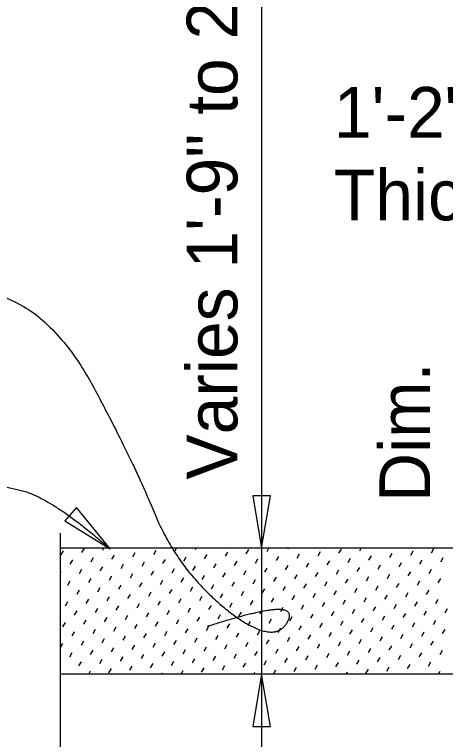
# Model space of a CAD drawing. Extents: x 0 to 41.1, y 0 to 25.9.
# Drawn here: x 3.953 to 5.668, y 17.261 to 20.145 of the extents above; entities that cross this region are included whole.
import ezdxf

# ---------------------------------------------------------------- set-up
doc = ezdxf.new("R2010")
doc.units = 0
for name, color, linetype in [('Dimension', 7, 'Continuous'), ('ExistSuperStruct', 7, 'Continuous'), ('Miscellaneous', 7, 'Continuous'), ('TextStructures', 7, 'Continuous')]:
    doc.layers.add(name, color=color, linetype=linetype)

msp = doc.modelspace()

# ---------------------------------------------------------------- linework, layer by layer
at = {"layer": 'Dimension'}
msp.add_line((4.936, 23.3552), (4.936, 16.3552), dxfattribs=at)
for points in [[(4.936, 18.0218), (4.9712, 18.2301), (4.9007, 18.2301)], [(4.3332, 18.0199), (4.1998, 18.1836), (4.1533, 18.1305)], [(4.936, 17.5218), (4.9007, 17.3136), (4.9712, 17.3136)]]:
    msp.add_lwpolyline(points, close=True, dxfattribs=at)
msp.add_lwpolyline([(4.1358, 16.1947), (4.1358, 17.0945), (4.0325, 17.0945), (4.1358, 17.1395), (4.2391, 17.1845), (4.1358, 17.1845), (4.1358, 18.0815)], dxfattribs=at)
for points in [[(2.6424, 19.1697), (3.0627, 19.1697), (3.7101, 19.0924), (4.1159, 18.9475), (4.4299, 18.3581), (4.5748, 18.0006), (4.8018, 17.7591), (4.9951, 17.6624), (5.0724, 17.7784), (4.9323, 17.7784), (4.7197, 17.7108)], [(3.0724, 18.3484), (3.3332, 18.3484), (3.6038, 18.3484), (3.8598, 18.2808), (4.1014, 18.2228), (4.3332, 18.0199)]]:
    msp.add_open_spline(points, degree=2, dxfattribs=at)
at = {"layer": 'ExistSuperStruct'}
msp.add_line((8.069, 17.5218), (4.1357, 17.5218), dxfattribs=at)
at = {"layer": 'Miscellaneous'}
for p, q in [((8.1278, 18.0218), (4.1357, 18.0218)), ((4.1385, 17.9954), (4.1482, 18.0122)), ((4.2214, 18.0051), (4.2311, 18.0218)), ((4.3044, 18.0148), (4.3084, 18.0218)), ((4.341, 17.9782), (4.3507, 17.995)), ((4.4239, 17.9879), (4.4336, 18.0047)), ((4.5068, 17.9976), (4.5166, 18.0144)), ((4.5898, 18.0074), (4.5981, 18.0218)), ((4.6727, 18.0171), (4.6755, 18.0218)), ((4.7093, 17.9805), (4.719, 17.9973)), ((4.7923, 17.9902), (4.802, 18.007)), ((4.8752, 17.9999), (4.8849, 18.0167)), ((4.9581, 18.0097), (4.9652, 18.0218)), ((5.0411, 18.0194), (5.0425, 18.0218)), ((5.0777, 17.9828), (5.0874, 17.9996)), ((5.1606, 17.9925), (5.1703, 18.0093)), ((5.2436, 18.0022), (5.2533, 18.019)), ((5.3265, 18.0119), (5.3322, 18.0218)), ((5.4094, 18.0217), (5.4095, 18.0218)), ((5.446, 17.9851), (5.4558, 18.0018)), ((5.529, 17.9948), (5.5387, 18.0116)), ((5.6119, 18.0045), (5.6216, 18.0213)), ((4.1751, 17.9588), (4.1848, 17.9756)), ((4.258, 17.9685), (4.2678, 17.9853)), ((4.4605, 17.9513), (4.4702, 17.9681)), ((4.5434, 17.961), (4.5532, 17.9778)), ((4.6264, 17.9708), (4.6361, 17.9876)), ((4.8289, 17.9536), (4.8386, 17.9704)), ((4.9118, 17.9633), (4.9215, 17.9801)), ((4.9947, 17.973), (5.0045, 17.9898)), ((5.1972, 17.9559), (5.207, 17.9727)), ((5.2802, 17.9656), (5.2899, 17.9824)), ((5.3631, 17.9753), (5.3728, 17.9921)), ((5.5656, 17.9582), (5.5753, 17.975)), ((5.6485, 17.9679), (5.6582, 17.9847)), ((4.2117, 17.9221), (4.2214, 17.9389)), ((4.2946, 17.9319), (4.3044, 17.9487)), ((4.3776, 17.9416), (4.3873, 17.9584)), ((4.5801, 17.9244), (4.5898, 17.9412)), ((4.663, 17.9342), (4.6727, 17.9509)), ((4.7459, 17.9439), (4.7557, 17.9607)), ((4.9484, 17.9267), (4.9581, 17.9435)), ((5.0314, 17.9364), (5.0411, 17.9532)), ((5.1143, 17.9462), (5.124, 17.963)), ((5.3168, 17.929), (5.3265, 17.9458)), ((5.3997, 17.9387), (5.4094, 17.9555)), ((5.4826, 17.9484), (5.4924, 17.9652)), ((5.6022, 17.9216), (5.6119, 17.9384)), ((4.1357, 17.9244), (4.1385, 17.9292)), ((4.3312, 17.8953), (4.341, 17.9121)), ((4.4142, 17.905), (4.4239, 17.9218)), ((4.4971, 17.9147), (4.5068, 17.9315)), ((4.6996, 17.8975), (4.7093, 17.9143)), ((4.7825, 17.9073), (4.7923, 17.9241)), ((4.8655, 17.917), (4.8752, 17.9338)), ((5.068, 17.8998), (5.0777, 17.9166)), ((5.1509, 17.9096), (5.1606, 17.9263)), ((5.2338, 17.9193), (5.2436, 17.9361)), ((5.3534, 17.8924), (5.3631, 17.9092)), ((5.4363, 17.9021), (5.446, 17.9189)), ((5.5193, 17.9118), (5.529, 17.9286)), ((4.1654, 17.8758), (4.1751, 17.8926)), ((4.2483, 17.8855), (4.258, 17.9023)), ((4.4508, 17.8684), (4.4605, 17.8852)), ((4.5337, 17.8781), (4.5434, 17.8949)), ((4.6167, 17.8878), (4.6264, 17.9046)), ((4.8191, 17.8707), (4.8289, 17.8875)), ((4.9021, 17.8804), (4.9118, 17.8972)), ((4.985, 17.8901), (4.9947, 17.9069)), ((5.1046, 17.8632), (5.1143, 17.88)), ((5.1875, 17.8729), (5.1972, 17.8897)), ((5.2704, 17.8827), (5.2802, 17.8995)), ((5.4729, 17.8655), (5.4826, 17.8823)), ((5.5559, 17.8752), (5.5656, 17.892)), ((5.6388, 17.885), (5.6485, 17.9017)), ((4.202, 17.8392), (4.2117, 17.856)), ((4.2849, 17.8489), (4.2946, 17.8657)), ((4.3679, 17.8587), (4.3776, 17.8755)), ((4.5703, 17.8415), (4.5801, 17.8583)), ((4.6533, 17.8512), (4.663, 17.868)), ((4.7362, 17.8609), (4.7459, 17.8777)), ((4.8558, 17.8341), (4.8655, 17.8508)), ((4.9387, 17.8438), (4.9484, 17.8606)), ((5.0216, 17.8535), (5.0314, 17.8703)), ((5.2241, 17.8363), (5.2338, 17.8531)), ((5.3071, 17.8461), (5.3168, 17.8629)), ((5.39, 17.8558), (5.3997, 17.8726)), ((5.5925, 17.8386), (5.6022, 17.8554)), ((4.3215, 17.8123), (4.3312, 17.8291)), ((4.4045, 17.822), (4.4142, 17.8388)), ((4.4874, 17.8318), (4.4971, 17.8486)), ((4.6069, 17.8049), (4.6167, 17.8217)), ((4.6899, 17.8146), (4.6996, 17.8314)), ((4.7728, 17.8243), (4.7825, 17.8411)), ((4.9753, 17.8072), (4.985, 17.824)), ((5.0582, 17.8169), (5.068, 17.8337)), ((5.1412, 17.8266), (5.1509, 17.8434)), ((5.3437, 17.8095), (5.3534, 17.8262)), ((5.4266, 17.8192), (5.4363, 17.836)), ((5.5095, 17.8289), (5.5193, 17.8457)), ((4.1556, 17.7929), (4.1654, 17.8097)), ((4.2386, 17.8026), (4.2483, 17.8194)), ((4.4411, 17.7854), (4.4508, 17.8022)), ((4.524, 17.7952), (4.5337, 17.812)), ((4.7265, 17.778), (4.7362, 17.7948)), ((4.8094, 17.7877), (4.8191, 17.8045)), ((4.8924, 17.7974), (4.9021, 17.8142)), ((5.0948, 17.7803), (5.1046, 17.7971)), ((5.1778, 17.79), (5.1875, 17.8068)), ((5.2607, 17.7997), (5.2704, 17.8165)), ((5.4632, 17.7826), (5.4729, 17.7994)), ((5.5461, 17.7923), (5.5559, 17.8091)), ((5.6291, 17.802), (5.6388, 17.8188)), ((4.1923, 17.7563), (4.202, 17.7731)), ((4.2752, 17.766), (4.2849, 17.7828)), ((4.3581, 17.7757), (4.3679, 17.7925)), ((4.4777, 17.7488), (4.4874, 17.7656)), ((4.5606, 17.7586), (4.5703, 17.7754)), ((4.6435, 17.7683), (4.6533, 17.7851)), ((4.846, 17.7511), (4.8558, 17.7679)), ((4.929, 17.7608), (4.9387, 17.7776)), ((5.0119, 17.7706), (5.0216, 17.7874)), ((5.2144, 17.7534), (5.2241, 17.7702)), ((5.2973, 17.7631), (5.3071, 17.7799)), ((5.3803, 17.7728), (5.39, 17.7896)), ((5.5827, 17.7557), (5.5925, 17.7725)), ((5.6657, 17.7654), (5.6754, 17.7822)), ((4.2289, 17.7197), (4.2386, 17.7365)), ((4.3118, 17.7294), (4.3215, 17.7462)), ((4.3947, 17.7391), (4.4045, 17.7559)), ((4.5972, 17.7219), (4.6069, 17.7387)), ((4.6802, 17.7317), (4.6899, 17.7485)), ((4.7631, 17.7414), (4.7728, 17.7582)), ((4.9656, 17.7242), (4.9753, 17.741)), ((5.0485, 17.734), (5.0582, 17.7507)), ((5.1315, 17.7437), (5.1412, 17.7605)), ((5.3339, 17.7265), (5.3437, 17.7433)), ((5.4169, 17.7362), (5.4266, 17.753)), ((5.4998, 17.746), (5.5095, 17.7628)), ((5.6194, 17.7191), (5.6291, 17.7359)), ((4.1459, 17.7099), (4.1556, 17.7267)), ((4.3484, 17.6928), (4.3581, 17.7096)), ((4.4313, 17.7025), (4.4411, 17.7193)), ((4.5143, 17.7122), (4.524, 17.729)), ((4.7168, 17.6951), (4.7265, 17.7119)), ((4.7997, 17.7048), (4.8094, 17.7216)), ((4.8826, 17.7145), (4.8924, 17.7313)), ((5.0851, 17.6973), (5.0948, 17.7141)), ((5.1681, 17.7071), (5.1778, 17.7239)), ((5.251, 17.7168), (5.2607, 17.7336)), ((5.3705, 17.6899), (5.3803, 17.7067)), ((5.4535, 17.6996), (5.4632, 17.7164)), ((5.5364, 17.7094), (5.5461, 17.7261)), ((4.1825, 17.6733), (4.1923, 17.6901)), ((4.2655, 17.6831), (4.2752, 17.6999)), ((4.468, 17.6659), (4.4777, 17.6827)), ((4.5509, 17.6756), (4.5606, 17.6924)), ((4.6338, 17.6853), (4.6435, 17.7021)), ((4.8363, 17.6682), (4.846, 17.685)), ((4.9192, 17.6779), (4.929, 17.6947)), ((5.0022, 17.6876), (5.0119, 17.7044)), ((5.1217, 17.6607), (5.1315, 17.6775)), ((5.2047, 17.6705), (5.2144, 17.6873)), ((5.2876, 17.6802), (5.2973, 17.697)), ((5.4901, 17.663), (5.4998, 17.6798)), ((5.573, 17.6727), (5.5827, 17.6895)), ((5.656, 17.6825), (5.6657, 17.6993)), ((4.2191, 17.6367), (4.2289, 17.6535)), ((4.3021, 17.6465), (4.3118, 17.6632)), ((4.385, 17.6562), (4.3947, 17.673)), ((4.5875, 17.639), (4.5972, 17.6558)), ((4.6704, 17.6487), (4.6802, 17.6655)), ((4.7534, 17.6585), (4.7631, 17.6753)), ((4.9559, 17.6413), (4.9656, 17.6581)), ((5.0388, 17.651), (5.0485, 17.6678)), ((5.2413, 17.6339), (5.251, 17.6506)), ((5.3242, 17.6436), (5.3339, 17.6604)), ((5.4072, 17.6533), (5.4169, 17.6701)), ((5.6096, 17.6361), (5.6194, 17.6529)), ((4.1362, 17.627), (4.1459, 17.6438)), ((4.3387, 17.6098), (4.3484, 17.6266)), ((4.4216, 17.6196), (4.4313, 17.6364)), ((4.5046, 17.6293), (4.5143, 17.6461)), ((4.707, 17.6121), (4.7168, 17.6289)), ((4.79, 17.6218), (4.7997, 17.6386)), ((4.8729, 17.6316), (4.8826, 17.6484)), ((4.9925, 17.6047), (5.0022, 17.6215)), ((5.0754, 17.6144), (5.0851, 17.6312)), ((5.1583, 17.6241), (5.1681, 17.6409)), ((5.3608, 17.607), (5.3705, 17.6238)), ((5.4438, 17.6167), (5.4535, 17.6335)), ((5.5267, 17.6264), (5.5364, 17.6432)), ((4.1728, 17.5904), (4.1825, 17.6072)), ((4.2557, 17.6001), (4.2655, 17.6169)), ((4.4582, 17.583), (4.468, 17.5998)), ((4.5412, 17.5927), (4.5509, 17.6095)), ((4.6241, 17.6024), (4.6338, 17.6192)), ((4.7436, 17.5755), (4.7534, 17.5923)), ((4.8266, 17.5852), (4.8363, 17.602)), ((4.9095, 17.595), (4.9192, 17.6118)), ((5.112, 17.5778), (5.1217, 17.5946)), ((5.1949, 17.5875), (5.2047, 17.6043)), ((5.2779, 17.5972), (5.2876, 17.614)), ((5.4804, 17.5801), (5.4901, 17.5969)), ((5.5633, 17.5898), (5.573, 17.6066)), ((5.6462, 17.5995), (5.656, 17.6163)), ((4.2094, 17.5538), (4.2191, 17.5706)), ((4.2924, 17.5635), (4.3021, 17.5803)), ((4.3753, 17.5732), (4.385, 17.59)), ((4.4948, 17.5464), (4.5046, 17.5631)), ((4.5778, 17.5561), (4.5875, 17.5729)), ((4.6607, 17.5658), (4.6704, 17.5826)), ((4.8632, 17.5486), (4.8729, 17.5654)), ((4.9461, 17.5584), (4.9559, 17.5752)), ((5.0291, 17.5681), (5.0388, 17.5849)), ((5.2316, 17.5509), (5.2413, 17.5677)), ((5.3145, 17.5606), (5.3242, 17.5774)), ((5.3974, 17.5704), (5.4072, 17.5872)), ((5.5999, 17.5532), (5.6096, 17.57)), ((4.1357, 17.56), (4.1362, 17.5609)), ((4.2487, 17.5218), (4.2557, 17.534)), ((4.329, 17.5269), (4.3387, 17.5437)), ((4.4119, 17.5366), (4.4216, 17.5534)), ((4.6157, 17.5218), (4.6241, 17.5363)), ((4.6973, 17.5292), (4.707, 17.546)), ((4.7803, 17.5389), (4.79, 17.5557)), ((4.9828, 17.5218), (4.9925, 17.5385)), ((5.0657, 17.5315), (5.0754, 17.5483)), ((5.1486, 17.5412), (5.1583, 17.558)), ((5.3511, 17.524), (5.3608, 17.5408)), ((5.434, 17.5338), (5.4438, 17.5506)), ((5.517, 17.5435), (5.5267, 17.5603)), ((5.6395, 17.5218), (5.6462, 17.5334)), ((4.1714, 17.5218), (4.1728, 17.5243)), ((4.5384, 17.5218), (4.5412, 17.5265)), ((4.9055, 17.5218), (4.9095, 17.5288)), ((5.2725, 17.5218), (5.2779, 17.5311)), ((5.5622, 17.5218), (5.5633, 17.5237))]:
    msp.add_line(p, q, dxfattribs=at)

# ---------------------------------------------------------------- texts
at = {"layer": 'Dimension'}
for s, p in [('1\'-2" x 10" x ', (5.2236, 19.6552)), ('Thick Neoprene Pad', (5.2236, 19.3263))]:
    msp.add_text(s, height=0.2016, dxfattribs=at).set_placement(p)
at = {"layer": 'TextStructures'}
for s, p in [('Varies 1\'-9" to 2\'-0"', (4.8397, 18.2953)), ('Dim.', (5.6063, 18.2066))]:
    msp.add_text(s, height=0.2016, rotation=90, dxfattribs=at).set_placement(p)

doc.saveas('drawing.dxf')
